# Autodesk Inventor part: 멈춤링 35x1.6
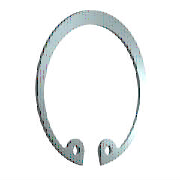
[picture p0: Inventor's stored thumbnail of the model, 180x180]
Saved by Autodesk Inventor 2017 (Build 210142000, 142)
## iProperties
IsCustomPart: 1
Created: 2015-09
Part Number: 멈춤링 35x1.6
Material: 강철, 연강
Description: 리테이닝 링(C형)
Document SubType Name: Modeling
Standard: KS B 1336
Designer: mduedu
Standards Organization: KS
Language: ko-KR
Size Designation: 35x1.6
Categories: <MemberInstance><Categories><Category DisplayName="샤프트 부품" InternalName="7f7aeb1f-a693-4053-b835-cee3144e0d98" Mnemonic="SHFT"><Category DisplayName="써클립" Inter
Density: 7.86 g/cm^3
Mass: 3.5371 g
Surface Area: 9.09651 cm^2
Volume: 0.450013 cm^3
Appearance: 파란색 - 벽 페인트 - 광택
Author: mduedu
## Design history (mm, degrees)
sketch "스케치1"
  geometry: L1 (0, 15.113)-(0, -73.177) reference; L2 (-45.5, 0)-(45.5, 0) reference; L3 (-4.964, 1)-(1.502, 1); L4 (0, -2.5)-(-5.307, -2.5); L5 (0, -17.5)-(-8.583, -33.888); L6 (-8.583, -33.888)-(-21.772, -26.981); L7 (-7.377, -31.585)-(-17.631, -26.214); L8 (-5.162, -32.745)-(-6.29, -34.898); L9 (5.162, -32.745)-(6.29, -34.898); C1 r 1.25 at (-7.377, -31.585); C2 r 1.25 at (7.377, -31.585); A1 r 15.875 centre (0, -18.375) between (11.82, -28.972) and (-11.82, -28.972); A2 r 18.5 centre (0, -17.5) between (6.29, -34.898) and (-6.29, -34.898); A3 r 2.5 centre (-7.377, -31.585) between (-5.162, -32.745) and (-8.668, -29.444); A4 r 2.5 centre (-9.959, -27.303) between (-11.82, -28.972) and (-8.668, -29.444); A5 r 2.5 centre (9.959, -27.303) between (8.668, -29.444) and (11.82, -28.972); A6 r 2.5 centre (7.377, -31.585) between (8.668, -29.444) and (5.162, -32.745); 3 further points
  constraints: 15 point on circle, 14 end point, 9 symmetric about line, 8 centre point, 6 tangent, 4 coincident, 4 point on line, 3 perpendicular, 1 parallel, 4 other
  dimensions: "d8" = 0.875 distance of A1.centre L5.start (= 0.25 x SRB1); "d38" = 3.5 distance between parallel lines of L4 L3 (= SRB1); "d39" = 17.5 distance from line of L5.start L2 (= 0.5 x WD); "d43" = 18.5 radius of A2 (= 0.5 x ND); "d45" = 2.6 distance between parallel lines of L7 L6 (= 0.5 x SRB2); "d46" = 2.5 radius of A4 (= SD5); "d47" = 6.29 distance from line of L1 L8.end (= 0.17 x ND); "d48" = 2.5 diameter of C1 (= SD5); "d49" = 2.5 radius of A3 (= SD5)
extrude "본체" new body sketch "스케치1" distance "d2" = 1.6 (= SD); taper "d3" = 0 deg
workaxis "Work Axis1"
workaxis "Work Axis2"
workplane "Work Plane1"
body "Solid1"
other parameters: "WD" = 35 [user parameter; used in 3 equation terms], "SD" = 1.6 [user parameter; used in 1 equation term], "SRB1" = 3.5 [user parameter; used in 2 equation terms], "ND" = 37 [user parameter; used in 2 equation terms], "SRB2" = 5.2 [user parameter; used in 1 equation term], "SD5" = 2.5 [user parameter; used in 3 equation terms], "d50" = 0, "d51" = 0, "d52" = 0, "d53" = 0, "WDMIN" = 34 [user parameter], "SD6" = 37.8 [user parameter], "WDMAX" = 35 (= WD) [user parameter], "NND" = 35 (= WD) [user parameter]
